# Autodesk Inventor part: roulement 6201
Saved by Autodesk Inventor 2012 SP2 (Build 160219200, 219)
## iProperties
Created: 2013-04
Part Number: roulement 6201
Material: Default
Document SubType Name: Modeling
Designer: papa
Density: 1 g/cm^3
Mass: 4.61945 g
Surface Area: 45.0424 cm^2
Volume: 4.61945 cm^3
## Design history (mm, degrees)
node "roulement 62011"
node "roulement 6201"
node "roulement 6201_1"
node "roulement 6201_2"
node "roulement 6201_3"
node "roulement 6201_4"
node "roulement 6201_5"
node "roulement 6201_6"
node "roulement 6201_7"
node "roulement 6201_8"
node "roulement 6201_9"
node "Base1"
node "Base2"
node "Base3"
node "Base4"
node "Base5"
node "Base6"
node "Base7"
node "Base8"
node "Base9"
node "Base10"
